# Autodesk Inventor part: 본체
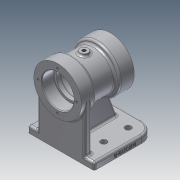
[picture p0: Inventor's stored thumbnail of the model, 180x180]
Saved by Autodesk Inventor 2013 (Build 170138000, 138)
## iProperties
Created: 2020-06
Part Number: 본체
Material: 알루미늄 6061
Document SubType Name: Modeling
Designer: user
Density: 2.71 g/cm^3
Mass: 728.075 g
Surface Area: 641.489 cm^2
Volume: 268.662 cm^3
Author: user
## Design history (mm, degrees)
sketch "스케치1"
  geometry: L1 (-39, 0)-(39, 0); L2 (-39, 0)-(-39, 35); L3 (-39, 35)-(-17, 35); L4 (-17, 35)-(-17, 29); L5 (-17, 29)-(17, 29); L6 (17, 29)-(17, 35); L7 (17, 35)-(39, 35); L8 (39, 35)-(39, 0); 2 further points
  constraints: 16 end point, 3 parallel, 3 perpendicular, 1 coincident, 1 collinear, 1 horizontal, 1 midpoint
  dimensions: "d0" = 78 distance of L1.start L1.end; "d1" = 70 diameter of L3 L1; "d2" = 70 diameter of L7 L1; "d3" = 22 distance between parallel lines of L4 L2; "d4" = 22 distance between parallel lines of L8 L6; "d5" = 58 diameter of L5 L1
revolve "회전1" sketch "스케치1" stored, may be unused: angle "d6" = 90 deg
sketch "스케치2"
  geometry: L1 (-39, -35)-(-39, 35) reference; L2 (-39, 35)-(-17, 35) reference; L3 (-17, 35)-(-17, 29) reference; L4 (-17, 29)-(17, 29) reference; L5 (17, 29)-(17, 35) reference; L6 (17, 35)-(39, 35) reference; L7 (39, 35)-(39, -35) reference; L8 (39, -35)-(17, -35) reference; L9 (17, -35)-(17, -29) reference; L10 (17, -29)-(-17, -29) reference; L11 (-17, -29)-(-17, -35) reference; L12 (-17, -35)-(-39, -35) reference; L13 (-39, 0)-(39, 0); L14 (-39, 0)-(-39, 23.5); L15 (-39, 23.5)-(-21, 23.5); L16 (-21, 23.5)-(-21, 20); L17 (-21, 20)-(-15, 20); L18 (-15, 20)-(-15, 23); L19 (-15, 23)-(15, 23); L20 (15, 23)-(15, 20); L21 (15, 20)-(21, 20); L22 (21, 20)-(21, 23.5); L23 (21, 23.5)-(39, 23.5); L24 (39, 23.5)-(39, 0); 1 further point
  constraints: 24 end point, 6 parallel, 4 perpendicular, 2 midpoint, 2 point on line
  dimensions: "d7" = 47 diameter of L23 L13; "d10" = 40 diameter of L21 L13; "d11" = 46 diameter of L19 L13; "d12" = 40 diameter of L17 L13; "d13" = 47 diameter of L15 L13; "d14" = 18 distance between parallel lines of L16 L1; "d15" = 6 distance between parallel lines of L18 L16; "d16" = 30 distance between parallel lines of L20 L18; "d17" = 18 distance between parallel lines of L7 L22
revolve "회전2" sketch "스케치2" stored, may be unused: angle "d18" = 90 deg
node "작업 평면1"
sketch "스케치3"
  geometry: L1 (-39, 35)-(-39, -35) reference; L2 (-34, 49)-(56, 49); L3 (56, 49)-(56, -49); L4 (56, -49)-(-34, -49); L5 (-34, -49)-(-34, 49); 2 further points
  constraints: 8 end point, 2 parallel, 1 horizontal, 1 horizontal alignment, 1 midpoint, 1 perpendicular
  dimensions: "d20" = 90 distance of L3.end L4.end; "d21" = 98 distance of L2.end L3.end; "d22" = 5 distance between parallel lines of L5 L1
extrude "돌출1" join sketch "스케치3" distance "d23" = 10; taper "d24" = 0 deg
sketch "스케치4"
  geometry: L1 (34, -49)-(34, 49) reference; L2 (34, -35)-(24, -35); L3 (24, -35)-(24, 35); L4 (24, 35)-(34, 35); L5 (34, 35)-(34, -35); 4 further points
  constraints: 8 end point, 3 midpoint, 2 parallel, 1 coincident, 1 horizontal, 1 horizontal alignment, 1 perpendicular
  dimensions: "d25" = 10 distance of L3.end L4.end; "d26" = 70 distance of L2.end L3.end
extrude "돌출2" join sketch "스케치4" stored distance "d27" = 10; taper "d28" = 0 deg
sketch "스케치5"
  geometry: L1 (39, 23.5)-(21, 23.5) reference; L2 (21, 23.5)-(21, 20) reference; L3 (21, 20)-(15, 20) reference; L4 (15, 20)-(15, 23) reference; L5 (15, 23)-(-15, 23) reference; L6 (-15, 23)-(-15, 20) reference; L7 (-15, 20)-(-21, 20) reference; L8 (-21, 20)-(-21, 23.5) reference; L9 (-21, 23.5)-(-39, 23.5) reference; L10 (-39, 23.5)-(-39, 35) reference; L11 (-39, 35)-(-17, 35) reference; L12 (-17, 35)-(-17, 29) reference; L13 (-17, 29)-(17, 29) reference; L14 (17, 29)-(17, 35) reference; L15 (17, 35)-(39, 35) reference; L16 (39, 35)-(39, 23.5) reference; L17 (21, -23.5)-(39, -23.5) reference; L18 (39, -23.5)-(39, -35) reference; L19 (39, -35)-(34, -35) reference; L20 (34, -35)-(34, -80) reference; L21 (34, -80)-(-56, -80) reference; L22 (-56, -80)-(-56, -70) reference; L23 (-56, -70)-(24, -70) reference; L24 (24, -70)-(24, -35) reference; L25 (24, -35)-(17, -35) reference; L26 (17, -35)-(17, -29) reference; L27 (17, -29)-(-17, -29) reference; L28 (-17, -29)-(-17, -35) reference; L29 (-17, -35)-(-39, -35) reference; L30 (-39, -35)-(-39, -23.5) reference; L31 (-39, -23.5)-(-21, -23.5) reference; L32 (-21, -23.5)-(-21, -20) reference; L33 (-21, -20)-(-15, -20) reference; L34 (-15, -20)-(-15, -23) reference; L35 (-15, -23)-(15, -23) reference; L36 (15, -23)-(15, -20) reference; L37 (15, -20)-(21, -20) reference; L38 (21, -20)-(21, -23.5) reference; L39 (-31.261, -35)-(-44, -70); 1 further point
  constraints: 2 end point, 2 point on line
  dimensions: "d29" = 12 distance from line of L22 L39.end; "d30" = 70 deg angle of L23 L39
feature "리브1" sketch "스케치5" dims "d31" = 1, "d32" = 10, "d33" = 0, "d34" = 0, "d35" = 1, "d36" = 1
sketch "스케치6"
  geometry: L1 (34, 49)-(34, -49) reference; 5 further points
  constraints: 2 horizontal alignment, 1 vertical alignment
  dimensions: "d37" = 58 distance of point (-36, 29) point (-36, -29); "d39" = 29 vertical distance of point (-36, -29) point (0, 0); "d40" = 29 vertical distance of point (-36, 29) point (0, 0); "d41" = 36 distance of point (-36, -29) point (0, -29); "d42" = 70 distance from line of L1 point (-36, -29)
hole "구멍1" sketch "스케치6" at (-36, -29), (0, -29), (0, 29), (-36, 29) diameter "d43" = 9; stored, may be unused: countersink angle "d47" = 90 deg, drill point angle "d49" = 118 deg; dims "d44" = 6, "d45" = 4, "d46" = 2, "d48" = 8
sketch "스케치7"
  geometry: C1 r 23.5 at (0, 0) reference; C2 r 35 at (0, 0) reference; A1 r 28.5 centre (0, 0) between (0, 28.5) and (28.5, 0); 2 further points
  constraints: 4 point on circle, 2 horizontal alignment, 2 vertical alignment, 1 centre point, 1 coincident
  dimensions: "d50" = 57 diameter of A1
hole "구멍2" sketch "스케치7" at (0, 28.5), (28.5, 0), (0, -28.5), (-28.5, 0) diameter "d51" = 3.242; stored, may be unused: countersink angle "d55" = 90 deg, drill point angle "d57" = 118 deg; dims "d52" = 10, "d53" = 4, "d54" = 2, "d56" = 12
fillet "모깎기1" dims "d58" = 20
fillet "모깎기2" dims "d59" = 0.3
fillet "모깎기3" dims "d60" = 3
chamfer "모따기1" distance "d61" = 1; stored, may be unused: second distance "d62" = 2, angle "d63" = 45 deg
node "작업 평면3"
  node "작업 평면2"
sketch "스케치8"
  geometry: C1 r 6 at (0, 0); 1 further point
  constraints: 1 centre point, 1 coincident
  dimensions: "d65" = 12 diameter of C1
extrude "돌출3" join sketch "스케치8" stored distance "d66" = 10; taper "d67" = 0 deg
sketch "스케치9"
  geometry: C1 r 6 at (0, 0) reference; 1 further point
  constraints: 1 coincident
hole "구멍3" sketch "스케치9" at (0, 0) diameter "d68" = 5.188; stored, may be unused: countersink angle "d72" = 90 deg, drill point angle "d74" = 118 deg; dims "d69" = 10, "d70" = 4, "d71" = 2, "d73" = 12
fillet "모깎기4" dims "d75" = 3
fillet "모깎기5" dims "d76" = 3
fillet "모깎기6" dims "d77" = 3
fillet "모깎기7" dims "d78" = 3
fillet "모깎기8" dims "d79" = 3
fillet "모깎기9" dims "d80" = 3
fillet "모깎기10" dims "d81" = 3
fillet "모깎기11" dims "d82" = 3
sketch "스케치10"
  geometry: L1 (67, 0)-(0, 0) reference; L2 (-3, 7)-(-3, 0) reference; 2 further points
  constraints: 1 other
  dimensions: "d83" = 4 distance from line of L1 point (42, 4); "d84" = 45 distance from line of L2 point (42, 4)
feature "엠보싱1" sketch "스케치10" dims "d0" = 78, "d1" = 70, "d2" = 70, "d3" = 22, "d4" = 22, "d5" = 58, "d7" = 47, "d10" = 40, "d11" = 46, "d12" = 40, "d13" = 47, "d14" = 18, "d15" = 6, "d16" = 30, "d17" = 18, "d85" = 0.5, "d86" = 0
fillet "모깎기12" dims "d87" = 3
node "솔리드1"
mirror "대칭1"
node "절단 모서리 투영1"
node "절단 모서리 투영2"
other parameters: "d64" = 3
